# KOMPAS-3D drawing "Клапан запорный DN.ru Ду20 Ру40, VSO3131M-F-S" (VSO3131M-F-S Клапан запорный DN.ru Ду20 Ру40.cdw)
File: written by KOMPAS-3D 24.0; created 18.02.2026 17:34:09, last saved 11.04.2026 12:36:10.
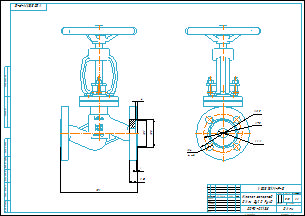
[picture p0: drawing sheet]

Document properties: Автор: R2D2; Форматы листов документа: A2; Полное имя файла: VSO3131M-F-S Клапан запорный DN.ru Ду20 Ру40.m3d; Масса: 5.15; Наименование: Клапан запорный DN.ru Ду20 Ру40; Количество листов документа: 1; Примечание: D090-02138

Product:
- Part/product: Клапан запорный DN.ru Ду20 Ру40  | designation VSO3131M-F-S
    Масса: 5.15
    Раздел спецификации: Прочие изделия
    Примечание: D090-02138

Referenced files in E:\Работа\Зайцев\Для компаса\: чертеж DN.ru А3.cdt
Referenced files in E:\Работа\Зайцев\VSO3131M-F-S Клапан запорный DN.ru Ду15-100 Ру40\DN20\: VSO3131M-F-S Клапан запорный DN.ru Ду20 Ру40.m3d
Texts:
  чертеж DN.ru А3.cdt
  Клапан запорный
  DN.ru Ду20 Ру40
  VSO3131M-F-S
  Клапан запорный DN.ru Ду20 Ру40
  VSO3131M-F-S Клапан запорный DN.ru Ду20 Ру40
Dimensions and other numbers on the sheet: 1:1; 0; 1; 2; 5,15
